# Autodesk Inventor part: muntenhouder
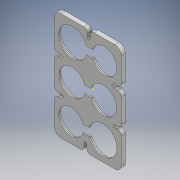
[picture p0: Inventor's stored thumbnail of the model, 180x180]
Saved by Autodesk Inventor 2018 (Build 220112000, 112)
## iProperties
Created: 2019-05
Part Number: muntenhouder
Material: Generic
Document SubType Name: Modeling
Designer: HP
Density: 1 g/cm^3
Appearance: Default
Author: HP
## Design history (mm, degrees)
sketch "Sketch1"
  geometry: L1 (-21, 42)-(21, 42); L2 (26, 37)-(26, -37); L3 (21, -42)-(-21, -42); L4 (-26, -37)-(-26, 37); L5 (-26, 42)-(26, -42); L6 (26, 42)-(-26, -42); A1 r 5 centre (21, 37) between (26, 37) and (21, 42); A2 r 5 centre (21, -37) between (21, -42) and (26, -37); A3 r 5 centre (-21, -37) between (-26, -37) and (-21, -42); A4 r 5 centre (-21, 37) between (-21, 42) and (-26, 37); 1 further point
  constraints: 12 end point, 8 point on circle, 8 point on line, 8 tangent, 4 centre point, 3 equal radius, 2 midpoint, 2 parallel, 1 horizontal, 1 perpendicular
  dimensions: "d0" = 52 distance of L5.start L6.start; "d1" = 84 distance of L6.end L5.start; "d2" = 5 radius of A1
extrude "Extrusion1" new body sketch "Sketch1" distance "d3" = 3; taper "d4" = 0 deg
sketch "Sketch2"
  geometry: L1 (-26, 37)-(-26, -37) reference; L2 (26, -37)-(26, 37) reference; L3 (-21, -42)-(21, -42) reference; L4 (21, 42)-(-21, 42) reference; C1 r 13 at (-11.75, -27); C2 r 11.75 at (13, -27); C3 r 13 at (11.75, 27); C4 r 12.25 at (12.25, 0); C5 r 11.75 at (-13, 27); C6 r 12.25 at (-12.25, 0); 1 further point
  constraints: 6 centre point, 4 horizontal alignment, 3 tangent
  dimensions: "d5" = 26 diameter of C1; "d6" = 26 diameter of C3; "d7" = 23.5 diameter of C2; "d8" = 23.5 diameter of C5 (= d7); "d9" = 24.5 diameter of C6 (= d10); "d10" = 24.5 diameter of C4; "d12" = 14.25 distance from line of L1 C1.centre; "d13" = 14.25 distance from line of C3.centre L2; "d14" = 13.75 distance from line of L1 C6.centre; "d15" = 15 distance from line of L3 C1.centre; "d16" = 15 distance from line of L4 C3.centre
extrude "Extrusion2" cut sketch "Sketch2" distance "d17" = 2.6; taper "d18" = 0 deg
sketch "Sketch4"
  geometry: 1 further point
sketch "Sketch5"
  geometry: L1 (26, -37)-(26, 37) reference; L2 (21, 42)-(-21, 42) reference; L3 (-26, 37)-(-26, -37) reference; L4 (-21, -42)-(21, -42) reference; A1 r 5 centre (21, 37) between (26, 37) and (21, 42) reference; A2 r 5 centre (-21, 37) between (-21, 42) and (-26, 37) reference; A3 r 5 centre (-21, -37) between (-26, -37) and (-21, -42) reference; A4 r 5 centre (21, -37) between (21, -42) and (26, -37) reference; 1 further point
extrude "Extrusion4" join sketch "Sketch5" distance "d26" = 0.4; taper "d27" = 0 deg
sketch "Sketch17"
  geometry: L1 (-2.311, -32)-(4.811, -32); L2 (4.811, -32)-(4.811, -22); L3 (4.811, -22)-(-2.311, -22); L4 (-2.311, -22)-(-2.311, -32); L5 (-2.311, -32)-(4.811, -22); L6 (4.811, -32)-(-2.311, -22); L7 (-4.811, -5)-(4.811, -5); L8 (4.811, -5)-(4.811, 5); L9 (4.811, 5)-(-4.811, 5); L10 (-4.811, 5)-(-4.811, -5); L11 (-4.811, -5)-(4.811, 5); L12 (4.811, -5)-(-4.811, 5); L13 (-4.766, 22)-(2.266, 22); L14 (2.266, 22)-(2.266, 32); L15 (2.266, 32)-(-4.766, 32); L16 (-4.766, 32)-(-4.766, 22); L17 (-4.766, 22)-(2.266, 32); L18 (2.266, 22)-(-4.766, 32); 3 further points
  constraints: 36 end point, 6 midpoint, 6 parallel, 3 horizontal, 3 perpendicular, 1 point on line
  dimensions: "d98" = 10 distance of L3.end L1.start; "d99" = 10 distance of L9.end L7.start; "d100" = 10 distance of L15.end L13.start; "d101" = 7.03108 distance of L14.end L15.end; "d102" = 9.62226 distance of L8.end L9.end
extrude "Extrusion14" cut sketch "Sketch17" stored distance "d103" = 2.4; taper "d104" = 0 deg
sketch "Sketch18"
  geometry: L1 (-26, 37)-(-26, -37) reference; L2 (-21, -42)-(21, -42) reference; L3 (26, -37)-(26, 37) reference; L4 (21, 42)-(-21, 42) reference; L5 (-1.167, -30)-(3.723, -30); L6 (3.723, -24)-(-1.167, -24); L7 (-2.449, -3)-(2.449, -3); L8 (2.449, 3)-(-2.449, 3); L9 (-3.723, 24)-(1.167, 24); L10 (1.167, 30)-(-3.723, 30); L11 (-2.367, 32)-(-0.25, 32) reference; L12 (-0.25, 22)-(-2.367, 22) reference; L13 (1.067, -5)-(-1.067, -5) reference; L14 (-1.067, 5)-(1.067, 5) reference; L15 (2.367, -32)-(0.25, -32) reference; L16 (0.25, -22)-(2.367, -22) reference; A1 r 5 centre (-21, -37) between (-26, -37) and (-21, -42) reference; A2 r 5 centre (21, -37) between (21, -42) and (26, -37) reference; A3 r 5 centre (21, 37) between (26, 37) and (21, 42) reference; A4 r 5 centre (-21, 37) between (-21, 42) and (-26, 37) reference; A5 r 11.75 centre (-13, 27) between (-2.367, 32) and (-2.367, 22) reference; A6 r 13 centre (11.75, 27) between (-0.25, 22) and (-0.25, 32) reference; A7 r 12.25 centre (12.25, 0) between (1.067, -5) and (1.067, 5) reference; A8 r 12.25 centre (-12.25, 0) between (-1.067, 5) and (-1.067, -5) reference; A9 r 11.75 centre (13, -27) between (2.367, -32) and (2.367, -22) reference; A10 r 13 centre (-11.75, -27) between (0.25, -22) and (0.25, -32) reference; A11 r 9.75 centre (13, -27) between (3.723, -30) and (3.723, -24); A12 r 11 centre (-11.75, -27) between (-1.167, -24) and (-1.167, -30); A13 r 10.25 centre (12.25, 0) between (2.449, -3) and (2.449, 3); A14 r 10.25 centre (-12.25, 0) between (-2.449, 3) and (-2.449, -3); A15 r 11 centre (11.75, 27) between (1.167, 24) and (1.167, 30); A16 r 9.75 centre (-13, 27) between (-3.723, 30) and (-3.723, 24); 1 further point
  constraints: 12 end point, 12 point on circle, 6 centre point
  dimensions: "d105" = 2 radial gap between concentric circles of A10 A12; "d106" = 2 radial gap between concentric circles of A8 A14; "d107" = 2 radial gap between concentric circles of A5 A16
extrude "Extrusion15" cut sketch "Sketch18" extent not by distance; stored distance "d108" = 2.4; taper "d109" = 0 deg
sketch "Sketch19"
  geometry: L1 (-26, 37)-(-26, -37) reference; L2 (-21, -42)-(21, -42) reference; L3 (26, -37)-(26, 37) reference; L4 (21, 42)-(-21, 42) reference; L5 (-26, 37)-(-26, -37) reference; L6 (-26, 12.25)-(-20.25, 12.25); L7 (-20.25, 12.25)-(-20.25, 15.25); L8 (-20.25, 15.25)-(-26, 15.25); L9 (21, -42)-(-21, -42) reference; L10 (-2.867, 42)-(-2.867, 36); L11 (-2.867, 36)-(-0.75, 36); L12 (-0.75, 36)-(-0.75, 42); L13 (-21, 42)-(21, 42) reference; L14 (26, 37)-(26, -37) reference; L15 (26, 12.25)-(20.25, 12.25); L16 (20.25, 12.25)-(20.25, 14); L17 (20.25, 14)-(26, 14); L18 (26, -15.25)-(20.25, -15.25); L19 (20.25, -15.25)-(20.25, -12.25); L20 (20.25, -12.25)-(26, -12.25); L21 (-26, -14)-(-20.25, -14); L22 (-20.25, -14)-(-20.25, -12.25); L23 (-20.25, -12.25)-(-26, -12.25); L24 (-0.25, -42)-(-0.25, -36); L25 (-0.25, -36)-(1.867, -36); L26 (1.867, -36)-(1.867, -42); L27 (-2.367, 32)-(-0.25, 32) reference; L28 (-0.25, 22)-(-2.367, 22) reference; L29 (1.067, -5)-(-1.067, -5) reference; L30 (-1.067, 5)-(1.067, 5) reference; L31 (2.367, -32)-(0.25, -32) reference; L32 (0.25, -22)-(2.367, -22) reference; A1 r 5 centre (-21, -37) between (-26, -37) and (-21, -42) reference; A2 r 5 centre (21, -37) between (21, -42) and (26, -37) reference; A3 r 5 centre (21, 37) between (26, 37) and (21, 42) reference; A4 r 5 centre (-21, 37) between (-21, 42) and (-26, 37) reference; A5 r 11.75 centre (-13, 27) between (-2.367, 32) and (-2.367, 22) reference; A6 r 13 centre (11.75, 27) between (-0.25, 22) and (-0.25, 32) reference; A7 r 12.25 centre (12.25, 0) between (1.067, -5) and (1.067, 5) reference; A8 r 12.25 centre (-12.25, 0) between (-1.067, 5) and (-1.067, -5) reference; A9 r 11.75 centre (13, -27) between (2.367, -32) and (2.367, -22) reference; A10 r 13 centre (-11.75, -27) between (0.25, -22) and (0.25, -32) reference; A11 r 12.25 centre (-12.25, 0) between (-1.067, 5) and (-1.067, -5) reference; A12 r 12.25 centre (12.25, 0) between (1.067, -5) and (1.067, 5) reference; 1 further point
  constraints: 36 end point, 12 perpendicular, 12 point on line, 8 tangent, 3 horizontal, 3 vertical
  dimensions: "d119" = 8 distance from line of L16 A7.centre; "d120" = 8 distance from line of A7.centre L19; "d121" = 8 distance from line of A8.centre L22; "d122" = 8 distance from line of A8.centre L7
extrude "Extrusion16" cut sketch "Sketch19" distance "d123" = 10; taper "d124" = 0 deg
fillet "Fillet7" dims "d125" = 3
sketch "Sketch21"
  geometry: L1 (2.367, -32)-(0.25, -32) reference; L2 (0.25, -22)-(2.367, -22) reference; L3 (1.067, -5)-(-1.067, -5) reference; L4 (-1.067, 5)-(1.067, 5) reference; L5 (-2.367, 32)-(-0.25, 32) reference; L6 (-0.25, 22)-(-2.367, 22) reference; L7 (-0.75, 39)-(-0.75, 36) reference; L8 (-0.75, 36)-(-2.867, 36) reference; L9 (-2.867, 36)-(-2.867, 39) reference; L10 (-5.867, 42)-(-21, 42) reference; L11 (-26, 37)-(-26, 18.25) reference; L12 (-23, 15.25)-(-20.25, 15.25) reference; L13 (-20.25, 15.25)-(-20.25, 12.25) reference; L14 (-20.25, 12.25)-(-23, 12.25) reference; L15 (-26, 9.25)-(-26, -9.25) reference; L16 (-23, -12.25)-(-20.25, -12.25) reference; L17 (-20.25, -12.25)-(-20.25, -14) reference; L18 (-20.25, -14)-(-23, -14) reference; L19 (-26, -17)-(-26, -37) reference; L20 (-21, -42)-(-3.25, -42) reference; L21 (-0.25, -39)-(-0.25, -36) reference; L22 (-0.25, -36)-(1.867, -36) reference; L23 (1.867, -36)-(1.867, -39) reference; L24 (4.867, -42)-(21, -42) reference; L25 (26, -37)-(26, -18.25) reference; L26 (23, -15.25)-(20.25, -15.25) reference; L27 (20.25, -15.25)-(20.25, -12.25) reference; L28 (20.25, -12.25)-(23, -12.25) reference; L29 (26, -9.25)-(26, 9.25) reference; L30 (23, 12.25)-(20.25, 12.25) reference; L31 (20.25, 12.25)-(20.25, 14) reference; L32 (20.25, 14)-(23, 14) reference; L33 (26, 17)-(26, 37) reference; L34 (21, 42)-(2.25, 42) reference; L35 (-0.75, 36)-(-1.808, 34.942); L36 (-2.867, 39)-(-2.867, 36) reference; L37 (-1.808, 34.942)-(-2.867, 36); L38 (20.25, 14)-(19.375, 13.125); L39 (20.25, 12.25)-(20.25, 14) reference; L40 (19.375, 13.125)-(20.25, 12.25); L41 (20.25, -12.25)-(18.75, -13.75); L42 (18.75, -13.75)-(20.25, -15.25); L43 (-20.25, -12.25)-(-20.25, -14) reference; L44 (-20.25, -12.25)-(-19.375, -13.125); L45 (-19.375, -13.125)-(-20.25, -14); L46 (1.867, -36)-(0.808, -34.942); L47 (0.808, -34.942)-(-0.25, -36); L48 (-20.25, 12.25)-(-20.25, 15.25) reference; L49 (-20.25, 15.25)-(-18.75, 13.75); L50 (-18.75, 13.75)-(-20.25, 12.25); A1 r 13 centre (-11.75, -27) between (0.25, -22) and (0.25, -32) reference; A2 r 11.75 centre (13, -27) between (2.367, -32) and (2.367, -22) reference; A3 r 12.25 centre (-12.25, 0) between (-1.067, 5) and (-1.067, -5) reference; A4 r 12.25 centre (12.25, 0) between (1.067, -5) and (1.067, 5) reference; A5 r 13 centre (11.75, 27) between (-0.25, 22) and (-0.25, 32) reference; A6 r 11.75 centre (-13, 27) between (-2.367, 32) and (-2.367, 22) reference; A7 r 3 centre (2.25, 39) between (2.25, 42) and (-0.75, 39) reference; A8 r 3 centre (-5.867, 39) between (-2.867, 39) and (-5.867, 42) reference; A9 r 5 centre (-21, 37) between (-21, 42) and (-26, 37) reference; A10 r 3 centre (-23, 18.25) between (-26, 18.25) and (-23, 15.25) reference; A11 r 3 centre (-23, 9.25) between (-23, 12.25) and (-26, 9.25) reference; A12 r 3 centre (-23, -9.25) between (-26, -9.25) and (-23, -12.25) reference; A13 r 3 centre (-23, -17) between (-23, -14) and (-26, -17) reference; A14 r 5 centre (-21, -37) between (-26, -37) and (-21, -42) reference; A15 r 3 centre (-3.25, -39) between (-3.25, -42) and (-0.25, -39) reference; A16 r 3 centre (4.867, -39) between (1.867, -39) and (4.867, -42) reference; A17 r 5 centre (21, -37) between (21, -42) and (26, -37) reference; A18 r 3 centre (23, -18.25) between (26, -18.25) and (23, -15.25) reference; A19 r 3 centre (23, -9.25) between (23, -12.25) and (26, -9.25) reference; A20 r 3 centre (23, 9.25) between (26, 9.25) and (23, 12.25) reference; A21 r 3 centre (23, 17) between (23, 14) and (26, 17) reference; A22 r 5 centre (21, 37) between (26, 37) and (21, 42) reference; 1 further point
  constraints: 24 end point, 1 parallel, 1 perpendicular
  dimensions: "d132" = 45 deg angle of L8 L35; "d133" = 45 deg angle of L8 L37; "d134" = 45 deg angle of L38 L31; "d135" = 45 deg angle of L31 L40; "d136" = 45 deg angle of L49 L13; "d137" = 45 deg angle of L13 L50; "d138" = 45 deg angle of L17 L44; "d139" = 45 deg angle of L17 L45; "d140" = 45 deg angle of L22 L47 (derived); "d141" = 45 deg angle of L42 L27; "d142" = 45 deg angle of L27 L41
extrude "Extrusion18" cut sketch "Sketch21" distance "d143" = 10; taper "d144" = 0 deg
body "Solid1"
node "Projected Loop14"
node "Projected Loop15"
node "Projected Loop16"
other parameters: "d36" = 1, "d61" = 0.2, "d65" = 0.2
